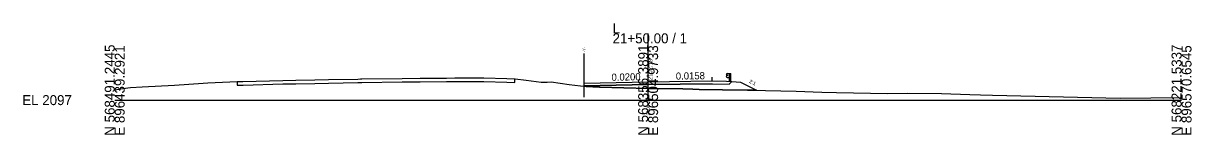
# Model space of a CAD drawing. Extents: x -26 to 1603, y -10 to 13527.
# Drawn here: x -25.7 to 302.8, y 8990.3 to 9021.6 of the extents above; entities that cross this region are included whole.
import ezdxf

# ---------------------------------------------------------------- set-up
doc = ezdxf.new("R2010")
doc.units = 0
for name, color, linetype in [('Default', 7, 'Continuous'), ('Exist XS Center Line Elevation Label', 7, 'Continuous'), ('Exist XS Ground Line', 7, 'Continuous'), ('Old_Level_61', 7, 'Continuous'), ('Old_Level_63', 7, 'Continuous'), ('Prop XS Earthwork Shape', 7, 'Continuous'), ('Prop XS EOT Tick Mark', 7, 'Continuous'), ('Prop XS Finish Grade', 7, 'Continuous'), ('Prop XS Finish Grade Earthwork', 7, 'Continuous'), ('Prop XS Finish Grade Paved Shoulder', 7, 'Continuous'), ('Prop XS Finish Grade Pavement', 7, 'Continuous'), ('Prop XS Guardrail', 7, 'Continuous'), ('Prop XS Shear Point Element', 7, 'Continuous'), ('Prop XS Shear Point Label', 7, 'Continuous'), ('Prop XS Side Slope Text', 7, 'Continuous'), ('Prop XS Subgrade Earthwork', 7, 'Continuous'), ('Prop XSC Text', 7, 'Continuous')]:
    doc.layers.add(name, color=color, linetype=linetype)

msp = doc.modelspace()

# ---------------------------------------------------------------- linework, layer by layer
at = {"layer": 'Exist XS Ground Line'}
for p, q in [((26.19, 9004.85), (34.47, 9005.19)), ((34.47, 9005.19), (35.26, 9005.22)), ((35.26, 9005.22), (36.02, 9005.23)), ((36.02, 9005.23), (47.26, 9005.54)), ((47.26, 9005.54), (50.93, 9005.61)), ((50.93, 9005.61), (56.29, 9005.71)), ((56.29, 9005.71), (60.16, 9005.78)), ((60.16, 9005.78), (68.37, 9005.93)), ((68.37, 9005.93), (69.12, 9005.94)), ((69.12, 9005.94), (69.47, 9005.95)), ((69.47, 9005.95), (80.87, 9006.09)), ((80.87, 9006.09), (85.9, 9006.16)), ((85.9, 9006.16), (93.29, 9006.21)), ((93.29, 9006.21), (95.68, 9006.22)), ((95.68, 9006.22), (103.75, 9006.25)), ((103.75, 9006.25), (110.25, 9006.04)), ((110.25, 9006.04), (112.58, 9005.97)), ((112.58, 9005.97), (115.66, 9005.62)), ((115.66, 9005.62), (119.88, 9005.05)), ((119.88, 9005.05), (121.61, 9005.08)), ((121.61, 9005.08), (122.73, 9005.1)), ((122.73, 9005.1), (127.83, 9004.39)), ((0, 9002.92), (2.32, 9003.3)), ((2.32, 9003.3), (4.45, 9003.56)), ((4.45, 9003.56), (7.74, 9003.77)), ((7.74, 9003.77), (16.82, 9004.23)), ((16.82, 9004.23), (24.86, 9004.76)), ((24.86, 9004.76), (26.19, 9004.85)), ((127.83, 9004.39), (132.55, 9003.78)), ((132.55, 9003.78), (136.33, 9003.66)), ((136.33, 9003.66), (150, 9003.3)), ((150, 9003.3), (151.58, 9003.26)), ((151.58, 9003.26), (159.76, 9003.13)), ((159.76, 9003.13), (162.61, 9003.1)), ((162.61, 9003.1), (164.34, 9003.01)), ((164.34, 9003.01), (170.91, 9002.93)), ((170.91, 9002.93), (177.94, 9002.84)), ((177.94, 9002.84), (183.04, 9002.71)), ((183.04, 9002.71), (191.64, 9002.54)), ((191.64, 9002.54), (198.83, 9002.22)), ((198.83, 9002.22), (202.97, 9002.13)), ((202.97, 9002.13), (217.34, 9001.89)), ((217.34, 9001.89), (223.06, 9001.92)), ((223.06, 9001.92), (232.49, 9001.86)), ((232.49, 9001.86), (240.49, 9001.56)), ((240.49, 9001.56), (243.49, 9001.48)), ((243.49, 9001.48), (246.87, 9001.39)), ((246.87, 9001.39), (282.7, 9000.54)), ((282.7, 9000.54), (291.33, 9000.68)), ((291.33, 9000.68), (300, 9000.71))]:
    msp.add_line(p, q, dxfattribs=at)
at = {"layer": 'Old_Level_61'}
for p, q in [((34.47, 9005.19), (34.47, 9004.19)), ((69.47, 9004.95), (80.87, 9005.09)), ((80.87, 9005.09), (85.9, 9005.16)), ((85.9, 9005.16), (93.29, 9005.21)), ((93.29, 9005.21), (95.68, 9005.22)), ((95.68, 9005.22), (103.75, 9005.25)), ((103.75, 9005.25), (110.25, 9005.04)), ((112.54, 9004.97), (112.54, 9005.97)), ((34.47, 9004.19), (35.26, 9004.22)), ((35.26, 9004.22), (36.02, 9004.23)), ((36.02, 9004.23), (36.15, 9004.24)), ((36.15, 9004.24), (47.26, 9004.54)), ((47.26, 9004.54), (50.93, 9004.61)), ((50.93, 9004.61), (56.29, 9004.71)), ((56.29, 9004.71), (60.16, 9004.78)), ((60.16, 9004.78), (68.37, 9004.93)), ((68.37, 9004.93), (69.12, 9004.94)), ((69.12, 9004.94), (69.47, 9004.95)), ((110.25, 9005.04), (112.54, 9004.97))]:
    msp.add_line(p, q, dxfattribs=at)
at = {"layer": 'Old_Level_63'}
for p, q in [((150, 9000), (150, 9018.76)), ((0, 9000), (150, 9000)), ((150, 9000), (300, 9000))]:
    msp.add_line(p, q, dxfattribs=at)
at = {"layer": 'Prop XS Earthwork Shape'}
msp.add_lwpolyline([(173.5, 9005.21), (176, 9005.01), (180.48, 9002.77), (177.94, 9002.84), (170.91, 9002.93), (164.34, 9003.01), (162.61, 9003.1), (159.76, 9003.13), (151.58, 9003.26), (150, 9003.3), (136.33, 9003.66), (132.55, 9003.78), (132, 9003.85), (132, 9003.98), (150, 9004.34), (168, 9004.62), (172.81, 9004.52)], close=True, dxfattribs=at)
at = {"layer": 'Prop XS EOT Tick Mark'}
for p, q in [((132, 9004.77), (132, 9005.77)), ((168, 9005.41), (168, 9006.41))]:
    msp.add_line(p, q, dxfattribs=at)
at = {"layer": 'Prop XS Finish Grade'}
msp.add_line((172, 9005.33), (173.5, 9005.21), dxfattribs=at)
at = {"layer": 'Prop XS Finish Grade Earthwork'}
for p, q in [((173.5, 9005.21), (176, 9005.01)), ((176, 9005.01), (180.48, 9002.77))]:
    msp.add_line(p, q, dxfattribs=at)
at = {"layer": 'Prop XS Finish Grade Paved Shoulder'}
msp.add_line((168, 9005.41), (172, 9005.33), dxfattribs=at)
at = {"layer": 'Prop XS Finish Grade Pavement'}
for p, q in [((132, 9004.77), (150, 9005.13)), ((150, 9005.13), (168, 9005.41))]:
    msp.add_line(p, q, dxfattribs=at)
at = {"layer": 'Prop XS Guardrail'}
for p, q in [((172, 9007.31), (171.97, 9007.25)), ((171.97, 9007.25), (172, 9007.19)), ((172, 9006.7), (171.97, 9006.64)), ((171.97, 9006.64), (172, 9006.58)), ((172.29, 9007.51), (172, 9007.31)), ((172, 9007.19), (172.29, 9006.99)), ((172.29, 9006.9), (172, 9006.7)), ((172, 9006.58), (172.29, 9006.38)), ((172.29, 9007.51), (173.29, 9007.51)), ((172.29, 9006.99), (172.29, 9006.9)), ((172.29, 9006.38), (172.79, 9006.38)), ((172.79, 9007.51), (172.79, 9005.27)), ((173.29, 9005.23), (173.29, 9007.51))]:
    msp.add_line(p, q, dxfattribs=at)
at = {"layer": 'Prop XS Shear Point Element'}
msp.add_line((132, 9000.84), (132, 9013.14), dxfattribs=at)
at = {"layer": 'Prop XS Subgrade Earthwork'}
for p, q in [((172.81, 9004.52), (173.5, 9005.21)), ((150, 9004.34), (132, 9003.98)), ((132, 9003.98), (132, 9003.85)), ((168, 9004.62), (150, 9004.34)), ((168, 9004.62), (172.81, 9004.52))]:
    msp.add_line(p, q, dxfattribs=at)

# ---------------------------------------------------------------- texts
at = {"layer": 'Default'}
for s, rotation, p in [('0.0200', 1.1458, (139.72, 9005.42)), ('0.0158', 0.9057, (157.8, 9005.75))]:
    msp.add_text(s, height=2, rotation=rotation, dxfattribs=at).set_placement(p)
at = {"layer": 'Exist XS Center Line Elevation Label'}
msp.add_text('2100.30', height=1, rotation=90, dxfattribs=at).set_placement((150.5, 8995.69))
at = {"layer": 'Old_Level_63'}
for s, p in [('L', (140, 9018.76)), ('21+50.00 / 1', (140, 9015.96)), ('EL 2097', (-26, 8998.6))]:
    msp.add_text(s, height=2.8, dxfattribs=at).set_placement(p)
for s, p in [('N 568491.2445', (0, 8990)), ('E 896439.2921', (2.8, 8990)), ('N 568356.3891', (150, 8990)), ('E 896504.9733', (152.8, 8990)), ('N 568221.5337', (300, 8990)), ('E 896570.6545', (302.8, 8990))]:
    msp.add_text(s, height=2.8, rotation=90, dxfattribs=at).set_placement(p)
at = {"layer": 'Prop XS Shear Point Label'}
msp.add_text(' -Y-', height=0.8, rotation=90, dxfattribs=at).set_placement((132.4, 9013.14))
at = {"layer": 'Prop XS Side Slope Text'}
msp.add_text('2:1', height=1, rotation=333.4443, dxfattribs=at).set_placement((178.31, 9004.94))
at = {"layer": 'Prop XSC Text'}
msp.add_text(' 2102.13', height=1.2, rotation=90, dxfattribs=at).set_placement((151.2, 9005.13))

doc.saveas('drawing.dxf')
